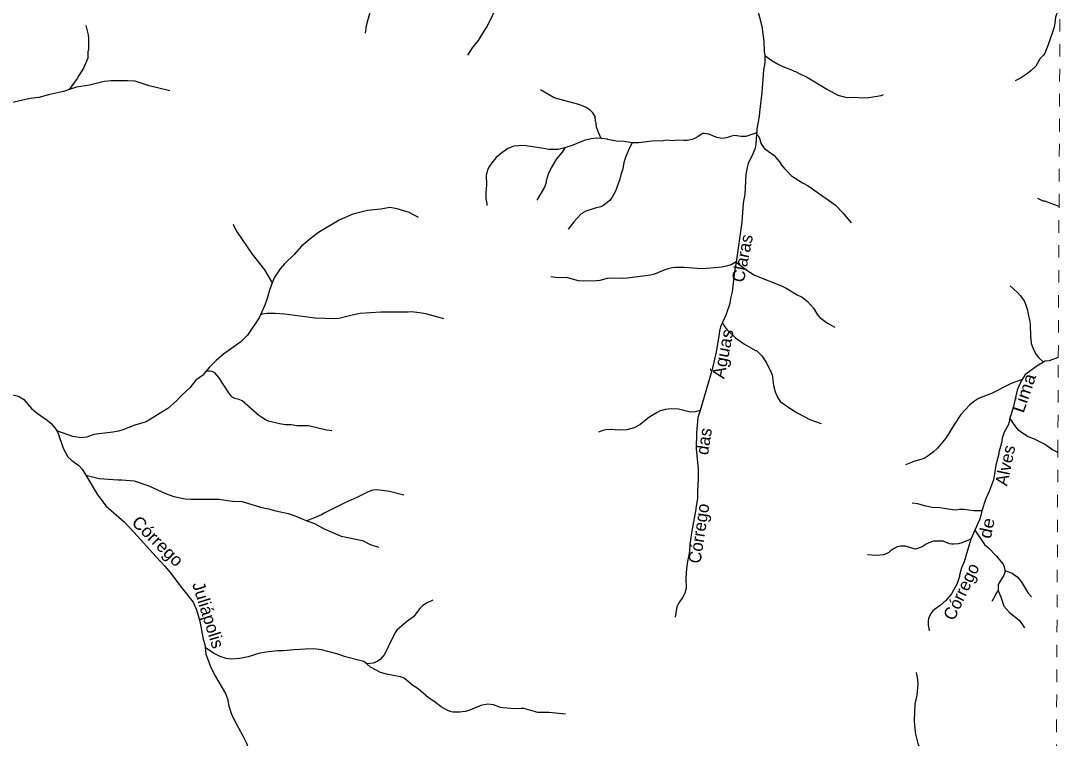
# Model space of a CAD drawing. Extents: x 551.6 to 577.6, y 7567 to 7594.7.
# Drawn here: x 569.17 to 577.56, y 7573.99 to 7579.74 of the extents above; entities that cross this region are included whole.
import ezdxf
from ezdxf.enums import TextEntityAlignment as Align

# ---------------------------------------------------------------- set-up
doc = ezdxf.new("R2010")
doc.units = 0
doc.header["$LTSCALE"] = 0.04
doc.linetypes.add('SHORT_DASHED', pattern=[2.7, 1.5, -1.2])
doc.layers.add('53', color=7, linetype='SHORT_DASHED', lineweight=13)
doc.layers.add('7', color=7, linetype='Continuous', lineweight=25)
doc.layers.add('61', color=7, linetype='Continuous')

msp = doc.modelspace()

# ---------------------------------------------------------------- linework, layer by layer
at = {"layer": '53'}
msp.add_lwpolyline([(577.4204, 7566.9518), (577.4226, 7567.3928), (577.4384, 7570.6314), (577.4446, 7571.9213), (577.4462, 7572.242), (577.4659, 7576.2813), (577.4696, 7577.0412), (577.4755, 7578.252), (577.4832, 7579.8317), (577.4989, 7583.0336), (577.5065, 7584.6034), (577.518, 7586.9644), (577.5184, 7587.0352), (577.519, 7587.1599), (577.5202, 7587.417), (577.5286, 7589.1281), (577.5292, 7589.2596), (577.5446, 7592.4063), (577.549, 7593.3187), (577.5554, 7594.6251)], dxfattribs=at)
at = {"layer": '7'}
msp.add_line((574.8908, 7577.8065), (574.8913, 7577.8061), dxfattribs=at)
for points in [[(574.8818, 7580.4167), (574.9687, 7580.1784), (575.0234, 7579.9611), (575.0572, 7579.8501), (575.0967, 7579.6939), (575.1136, 7579.5732), (575.1152, 7579.4944), (575.1196, 7579.461)], [(572.1544, 7580.2464), (572.1221, 7580.1929), (572.1109, 7580.1663), (572.1101, 7580.1462), (572.1004, 7580.1124), (572.0859, 7580.0336), (572.0014, 7579.9128), (571.9676, 7579.834), (571.9298, 7579.6972), (571.9201, 7579.64)], [(573.1451, 7580.075), (573.0573, 7580.0054), (573.0251, 7579.9611), (572.8972, 7579.6955), (572.8778, 7579.6682), (572.8263, 7579.5813), (572.7764, 7579.5201), (572.7394, 7579.463)], [(577.4832, 7579.8317), (577.4757, 7579.8275), (577.4604, 7579.805), (577.4475, 7579.7664), (577.4427, 7579.7181), (577.4354, 7579.6859), (577.3895, 7579.5443), (577.3614, 7579.4774), (577.3517, 7579.4622), (577.3236, 7579.4348), (577.289, 7579.3744), (577.2535, 7579.339), (577.2238, 7579.3157), (577.1666, 7579.2786), (577.1232, 7579.2577)], [(569.6844, 7579.6996), (569.7029, 7579.6263), (569.7069, 7579.5974), (569.7069, 7579.533), (569.7053, 7579.4992), (569.7021, 7579.4943), (569.7005, 7579.4388), (569.6675, 7579.3575), (569.6281, 7579.2996), (569.616, 7579.2754), (569.5521, 7579.1871)], [(575.1196, 7579.461), (575.12, 7579.401), (575.1104, 7579.3414)], [(575.1196, 7579.461), (575.1756, 7579.4203), (575.2158, 7579.3961), (575.2633, 7579.372), (575.347, 7579.3398), (575.3526, 7579.335), (575.3655, 7579.3326), (575.4049, 7579.3092), (575.4532, 7579.2883), (575.6206, 7579.1869), (575.7059, 7579.1418), (575.7542, 7579.129), (575.7832, 7579.1249), (575.846, 7579.1257), (575.891, 7579.1217), (575.9538, 7579.1249)], [(575.1104, 7579.3414), (575.0975, 7579.1636), (575.0766, 7579.0066), (575.0749, 7578.9728), (575.0572, 7578.8714), (575.0554, 7578.8444), (575.0545, 7578.8313)], [(570.3564, 7579.1773), (570.1914, 7579.2159), (570.0804, 7579.2545), (570.0176, 7579.2577), (569.8872, 7579.2577), (569.8309, 7579.2505), (569.7134, 7579.2223), (569.6104, 7579.2054), (569.5521, 7579.1871)], [(569.5521, 7579.1871), (569.5057, 7579.1724), (569.3866, 7579.1459)], [(573.8107, 7578.7942), (573.7889, 7578.8425), (573.7736, 7578.8859), (573.7688, 7578.9221), (573.7647, 7578.931), (573.7615, 7578.972), (573.743, 7579.0002), (573.7237, 7579.0187), (573.6907, 7579.0428), (573.6617, 7579.0581), (573.6118, 7579.0742), (573.541, 7579.0903), (573.4331, 7579.1217), (573.3245, 7579.1853)], [(569.3866, 7579.1459), (569.3078, 7579.1241), (569.2402, 7579.1145), (569.0776, 7579.0774), (568.9247, 7579.0171), (568.8571, 7578.9817), (568.7943, 7578.943), (568.651, 7578.832), (568.6289, 7578.8084)], [(575.9538, 7579.1249), (576.0504, 7579.1394), (576.0705, 7579.1467)], [(575.0554, 7578.8444), (575.0403, 7578.8344), (574.9687, 7578.8119), (574.9301, 7578.8111), (574.8786, 7578.8183), (574.8528, 7578.8135), (574.8142, 7578.8006), (574.7756, 7578.7942), (574.7369, 7578.8022), (574.6726, 7578.8288), (574.6339, 7578.836), (574.6219, 7578.8344), (574.5873, 7578.8102), (574.5631, 7578.7974), (574.5374, 7578.7877), (574.4987, 7578.7789), (574.473, 7578.7781), (574.4215, 7578.7829), (574.3828, 7578.7773), (574.3313, 7578.7813), (574.3056, 7578.7773), (574.2154, 7578.7732), (574.1112, 7578.7617), (574.0581, 7578.7602)], [(573.776, 7578.7974), (573.7309, 7578.7925), (573.6746, 7578.7789), (573.5845, 7578.7427), (573.5205, 7578.7215)], [(574.0581, 7578.7602), (574.0359, 7578.7201), (574.0078, 7578.6525), (573.9917, 7578.6042), (573.9836, 7578.5527), (573.9675, 7578.5044), (573.9595, 7578.469), (573.9249, 7578.3725), (573.8991, 7578.3242), (573.8798, 7578.3), (573.8243, 7578.2566), (573.8066, 7578.2477), (573.7615, 7578.2372), (573.6875, 7578.2131), (573.6505, 7578.1914), (573.5901, 7578.127), (573.5458, 7578.069)], [(574.0581, 7578.7602), (573.9949, 7578.77), (573.9305, 7578.7748), (573.8637, 7578.7861), (573.8599, 7578.7896), (573.8107, 7578.7942), (573.776, 7578.7974)], [(575.0545, 7578.8313), (575.0492, 7578.7523), (575.0419, 7578.7185), (575.0242, 7578.6735), (574.9864, 7578.5946), (574.9784, 7578.564), (574.9687, 7578.5061), (574.9591, 7578.3499), (574.9478, 7578.2775)], [(575.0545, 7578.8313), (575.0669, 7578.8167), (575.0766, 7578.7974), (575.0894, 7578.7588), (575.1047, 7578.7314), (575.1176, 7578.7153), (575.194, 7578.6582), (575.2383, 7578.6083), (575.256, 7578.5801), (575.2745, 7578.5584), (575.3341, 7578.4956), (575.421, 7578.4392), (575.4669, 7578.4151), (575.6576, 7578.2839), (575.6858, 7578.2606), (575.7445, 7578.2002), (575.8113, 7578.1206)], [(573.5205, 7578.7215), (573.4654, 7578.7072), (573.3913, 7578.7072), (573.3334, 7578.7185), (573.1901, 7578.7386), (573.1113, 7578.733), (573.0638, 7578.7153), (573.0147, 7578.6807), (572.9704, 7578.6421), (572.9342, 7578.601), (572.9157, 7578.5737), (572.9012, 7578.5447)], [(573.5205, 7578.7215), (573.4975, 7578.6863), (573.4533, 7578.6332), (573.4106, 7578.5608), (573.3849, 7578.5109), (573.3704, 7578.457), (573.3712, 7578.4441), (573.3559, 7578.4047), (573.2964, 7578.3024)], [(572.9012, 7578.5447), (572.8907, 7578.498), (572.8915, 7578.424), (572.8859, 7578.3596), (572.8867, 7578.3145), (572.8939, 7578.2759), (572.894, 7578.259)], [(574.9478, 7578.2775), (574.9365, 7578.1262), (574.8913, 7577.8061)], [(577.4755, 7578.252), (577.3606, 7578.2936), (577.3477, 7578.2944), (577.3045, 7578.3137)], [(572.3491, 7578.1624), (572.2743, 7578.2018), (572.1761, 7578.2332), (572.1181, 7578.2437), (572.0473, 7578.2292), (571.9395, 7578.2195), (571.8236, 7578.1881), (571.7117, 7578.1415), (571.5467, 7578.0433), (571.4775, 7577.9902), (571.4115, 7577.9338), (571.3519, 7577.867), (571.2763, 7577.7922)], [(570.8643, 7578.1093), (570.8739, 7578.0827), (570.8956, 7578.0441), (571.0163, 7577.8678), (571.1153, 7577.7447), (571.1756, 7577.6395)], [(571.2763, 7577.7922), (571.2417, 7577.752), (571.1934, 7577.6787), (571.1756, 7577.6395)], [(574.8908, 7577.8065), (574.8496, 7577.7849), (574.811, 7577.7721), (574.7756, 7577.7656), (574.6532, 7577.7535), (574.6162, 7577.7519), (574.4714, 7577.7624), (574.4054, 7577.7624), (574.3764, 7577.7592), (574.3185, 7577.7431), (574.238, 7577.7093), (574.2042, 7577.7004), (574.0175, 7577.6771)], [(574.8913, 7577.8061), (574.877, 7577.7302), (574.8576, 7577.5677), (574.8448, 7577.5129), (574.8399, 7577.4727), (574.8094, 7577.3809), (574.7822, 7577.3226)], [(574.8913, 7577.8061), (574.9768, 7577.7407), (575.0379, 7577.702), (575.2528, 7577.6143), (575.2906, 7577.5966), (575.3792, 7577.5443), (575.4194, 7577.5242), (575.4612, 7577.4888), (575.5087, 7577.4365), (575.5409, 7577.3842), (575.5594, 7577.3624), (575.6206, 7577.3165), (575.6794, 7577.2836)], [(574.0175, 7577.6771), (573.9772, 7577.6731), (573.8774, 7577.6771), (573.8581, 7577.6755), (573.8002, 7577.6578), (573.7728, 7577.6546), (573.6666, 7577.653), (573.6279, 7577.6562), (573.5314, 7577.6827), (573.4638, 7577.6803), (573.4066, 7577.6868)], [(571.1756, 7577.6395), (571.154, 7577.5805), (571.1363, 7577.5129), (571.1185, 7577.4614), (571.0842, 7577.3843)], [(577.0845, 7577.6143), (577.1441, 7577.5612), (577.165, 7577.5379), (577.1908, 7577.5033), (577.2012, 7577.484), (577.2238, 7577.4212), (577.2278, 7577.3874), (577.2415, 7577.3311), (577.2447, 7577.3085), (577.2463, 7577.2039), (577.2495, 7577.1975), (577.2527, 7577.1508), (577.256, 7577.1492), (577.2592, 7577.1331), (577.2729, 7577.0993), (577.293, 7577.0655), (577.3115, 7577.0413), (577.3512, 7577.0045)], [(571.0842, 7577.3843), (571.0727, 7577.3584), (570.9801, 7577.22), (570.9246, 7577.1668), (570.787, 7577.0687), (570.7274, 7577.018), (570.6711, 7576.9608), (570.6484, 7576.9313)], [(571.2779, 7577.3874), (571.2007, 7577.3946), (571.1363, 7577.3938), (571.0952, 7577.389), (571.0842, 7577.3843)], [(572.5519, 7577.3504), (572.4079, 7577.3906), (572.3563, 7577.4002), (572.292, 7577.4075), (572.2662, 7577.4043), (572.0473, 7577.4043), (571.8799, 7577.393), (571.8284, 7577.3833), (571.7093, 7577.3536), (571.6835, 7577.3503), (571.5194, 7577.356), (571.2779, 7577.3874)], [(574.7822, 7577.3226), (574.7659, 7577.2876), (574.7562, 7577.2538), (574.7514, 7577.2136)], [(574.7822, 7577.3226), (574.7957, 7577.2948), (574.815, 7577.2658), (574.8858, 7577.1999), (574.9575, 7577.1475), (575.0444, 7577.0984), (575.0524, 7577.0968), (575.0951, 7577.055), (575.1345, 7576.9995), (575.1715, 7576.9222), (575.178, 7576.9029), (575.1908, 7576.8176), (575.2021, 7576.7661), (575.2214, 7576.725), (575.244, 7576.6888), (575.3357, 7576.6244), (575.3856, 7576.5971)], [(574.7514, 7577.2136), (574.7305, 7577.088), (574.6999, 7576.9464), (574.6035, 7576.6173)], [(577.3512, 7577.0045), (577.297, 7576.9721), (577.2197, 7576.9158), (577.2028, 7576.8996), (577.1808, 7576.8652)], [(577.4696, 7577.0412), (577.3958, 7577.016), (577.3654, 7577.0129), (577.3512, 7577.0045)], [(570.6484, 7576.9313), (570.618, 7576.8964), (570.5657, 7576.8594), (570.5166, 7576.7999), (570.4522, 7576.7387), (570.4103, 7576.6936)], [(570.6952, 7576.9294), (570.6727, 7576.9327), (570.6484, 7576.9313)], [(571.6538, 7576.4538), (571.6111, 7576.4594), (571.4662, 7576.4932), (571.3745, 7576.494), (571.3294, 7576.5013), (571.2844, 7576.5029), (571.2361, 7576.5101), (571.1459, 7576.5319), (571.1234, 7576.5415), (571.0928, 7576.56), (571.0711, 7576.5777), (570.9375, 7576.6944), (570.9125, 7576.7065), (570.8787, 7576.7146), (570.8546, 7576.7258), (570.8296, 7576.758), (570.7507, 7576.8812), (570.7169, 7576.9182), (570.6952, 7576.9294)], [(568.6786, 7576.8276), (568.7187, 7576.8047), (568.7669, 7576.7822), (568.8458, 7576.7612), (568.8683, 7576.758), (569.0341, 7576.7548), (569.1355, 7576.7339), (569.1549, 7576.7274), (569.1886, 7576.7049), (569.2506, 7576.6341)], [(577.1808, 7576.8652), (577.087, 7576.8296), (576.9341, 7576.7532), (576.831, 7576.7121), (576.79, 7576.6864), (576.7586, 7576.6598), (576.6902, 7576.5842), (576.6395, 7576.5085), (576.5703, 7576.3959), (576.5018, 7576.3146), (576.4705, 7576.2856), (576.4286, 7576.2534), (576.3948, 7576.2333), (576.3127, 7576.21), (576.2476, 7576.1834)], [(577.1808, 7576.8652), (577.1642, 7576.8353), (577.1401, 7576.779), (577.1079, 7576.6373), (577.0826, 7576.5556)], [(570.4103, 7576.6936), (570.3403, 7576.6341), (570.1673, 7576.5254), (570.0772, 7576.4989), (569.9806, 7576.4618), (569.9468, 7576.4522), (569.9017, 7576.4425), (569.7488, 7576.4248), (569.6925, 7576.4039), (569.6474, 7576.3991), (569.5798, 7576.4079), (569.4526, 7576.4534)], [(569.2506, 7576.6341), (569.2941, 7576.5946), (569.3754, 7576.5407), (569.4075, 7576.5118), (569.4357, 7576.4796), (569.4526, 7576.4534)], [(574.6035, 7576.6173), (574.5631, 7576.6075), (574.5261, 7576.6043), (574.4295, 7576.6284), (574.3716, 7576.6292), (574.3233, 7576.6252), (574.2758, 7576.6115), (574.2581, 7576.6019), (574.1913, 7576.5617), (574.1189, 7576.5013), (574.0738, 7576.4771), (574.0158, 7576.4635), (573.9597, 7576.4586), (573.8806, 7576.4643), (573.8468, 7576.4618), (573.8243, 7576.4578), (573.7897, 7576.445)], [(574.6035, 7576.6173), (574.584, 7576.5601), (574.5727, 7576.4377), (574.5719, 7576.3122), (574.58, 7576.1995), (574.5872, 7576.1512)], [(575.3856, 7576.5971), (575.4806, 7576.5455), (575.5699, 7576.5134)], [(577.0826, 7576.5556), (577.0708, 7576.5053), (577.037, 7576.4442), (577.0209, 7576.3959), (577.0145, 7576.3572), (576.9944, 7576.28), (576.9944, 7576.2703), (576.9694, 7576.1786), (576.9582, 7576.111)], [(577.4659, 7576.2813), (577.4218, 7576.3025), (577.359, 7576.3484), (577.2729, 7576.391), (577.2286, 7576.4071), (577.19, 7576.4296), (577.1545, 7576.4578), (577.1288, 7576.4852), (577.0826, 7576.5556)], [(569.4526, 7576.4534), (569.4607, 7576.4409), (569.5033, 7576.3154), (569.5419, 7576.2462), (569.5725, 7576.2164), (569.6281, 7576.177), (569.6554, 7576.1464), (569.684, 7576.0985)], [(574.5872, 7576.1512), (574.5872, 7576.0691), (574.58, 7575.9677), (574.58, 7575.913), (574.5679, 7575.8341), (574.5687, 7575.8245), (574.5389, 7575.6683), (574.5212, 7575.546), (574.5164, 7575.4881), (574.5003, 7575.4092), (574.4923, 7575.3529), (574.4882, 7575.274), (574.4907, 7575.1935), (574.4794, 7575.1533), (574.4633, 7575.1227), (574.4392, 7575.0889)], [(569.684, 7576.0985), (569.7745, 7575.9468), (569.8462, 7575.8534), (569.9926, 7575.7255), (570.0691, 7575.6442)], [(569.684, 7576.0985), (569.7923, 7576.0723), (569.9419, 7576.0619), (569.9741, 7576.0627), (570.0707, 7576.0538), (570.1882, 7576.0144), (570.3218, 7575.9532), (570.3894, 7575.9291), (570.4812, 7575.9098), (570.5295, 7575.9065), (570.5906, 7575.9081)], [(576.9582, 7576.111), (576.9501, 7576.0627), (576.9195, 7575.9758), (576.8874, 7575.9049), (576.857, 7575.8146)], [(570.5906, 7575.9081), (570.75, 7575.9065), (570.8594, 7575.892), (570.9367, 7575.8872), (571.0832, 7575.8422), (571.1475, 7575.8309), (571.2055, 7575.8132), (571.3037, 7575.7915), (571.352, 7575.7762), (571.4553, 7575.7343), (571.4711, 7575.7279)], [(572.2316, 7575.9387), (572.1165, 7575.9693), (572.0167, 7575.9806), (571.9813, 7575.979), (571.9451, 7575.9653), (571.855, 7575.9194), (571.7584, 7575.8768), (571.5934, 7575.7947), (571.5717, 7575.781), (571.5081, 7575.7544), (571.4553, 7575.7343)], [(576.857, 7575.8146), (576.7924, 7575.8132), (576.7135, 7575.8244), (576.6797, 7575.8244), (576.6556, 7575.8196), (576.6234, 7575.8212), (576.522, 7575.8381), (576.456, 7575.8397), (576.3981, 7575.8526), (576.3449, 7575.8711), (576.3007, 7575.876)], [(576.857, 7575.8146), (576.8503, 7575.7762), (576.8383, 7575.7424), (576.8003, 7575.6586), (576.7702, 7575.5859)], [(571.4711, 7575.7279), (571.5145, 7575.711), (571.5886, 7575.6731), (571.7286, 7575.612), (571.9008, 7575.575), (571.9604, 7575.5452), (572.0272, 7575.5219)], [(576.8003, 7575.6586), (576.8777, 7575.5444), (576.9099, 7575.517), (576.971, 7575.4543), (577.0282, 7575.3867), (577.0359, 7575.3662), (577.0414, 7575.3366)], [(570.0691, 7575.6442), (570.247, 7575.4454), (570.3178, 7575.3714), (570.3612, 7575.3191), (570.4498, 7575.1991), (570.5431, 7575.0824), (570.5697, 7575.0213), (570.597, 7574.9311), (570.6252, 7574.7863), (570.6389, 7574.7444), (570.6398, 7574.7202)], [(576.7702, 7575.5859), (576.6974, 7575.5581), (576.6717, 7575.5508), (576.6363, 7575.5468), (576.6177, 7575.546), (576.5993, 7575.5508), (576.5477, 7575.5701), (576.4705, 7575.5701), (576.4319, 7575.5581), (576.4109, 7575.5476), (576.3795, 7575.5251), (576.3353, 7575.509), (576.3224, 7575.5074), (576.2451, 7575.5299), (576.2065, 7575.5299), (576.1808, 7575.5243), (576.1566, 7575.513), (576.1228, 7575.4905), (576.1131, 7575.48), (576.0729, 7575.4623), (576.0085, 7575.4567), (575.9433, 7575.4623)], [(576.7702, 7575.5859), (576.7167, 7575.406), (576.6942, 7575.3561), (576.6797, 7575.2981), (576.6797, 7575.2885), (576.6612, 7575.2321), (576.6145, 7575.1492), (576.5687, 7575.0945), (576.5244, 7575.0551), (576.4785, 7575.0245)], [(577.0414, 7575.3366), (577.0411, 7575.3191), (577.033, 7575.2997), (576.9888, 7575.2233), (576.9893, 7575.1771)], [(577.0414, 7575.3366), (577.1014, 7575.3142), (577.1401, 7575.286), (577.1714, 7575.2482), (577.2286, 7575.1549), (577.2544, 7575.1251)], [(576.9893, 7575.1771), (576.9719, 7575.1533), (576.9622, 7575.1291), (576.9381, 7575.0881)], [(576.9893, 7575.1771), (577.0129, 7575.1179), (577.0338, 7575.0502), (577.0757, 7575.0036), (577.1578, 7574.9368), (577.1996, 7574.8772)], [(572.4618, 7575.0977), (572.4167, 7575.0776), (572.3829, 7575.0551), (572.3587, 7575.0309), (572.3089, 7574.9649), (572.2517, 7574.9239), (572.1752, 7574.8587), (572.1632, 7574.8434), (572.1414, 7574.8032), (572.0746, 7574.6623), (572.0424, 7574.6221), (572.0223, 7574.6092), (571.9861, 7574.5947), (571.9352, 7574.5874)], [(574.4392, 7575.0889), (574.4311, 7575.0776), (574.4166, 7575.0438), (574.4038, 7574.9625)], [(576.4785, 7575.0245), (576.4656, 7575.014), (576.4479, 7574.9923), (576.4302, 7574.9521), (576.4302, 7574.9424), (576.427, 7574.9376), (576.427, 7574.9038), (576.4367, 7574.8531)], [(570.6398, 7574.7202), (570.6453, 7574.6656), (570.6823, 7574.5674)], [(571.4405, 7574.705), (571.352, 7574.7009), (571.2634, 7574.6921), (571.22, 7574.6937), (571.1459, 7574.6857), (571.0767, 7574.6736), (570.985, 7574.6454), (570.9174, 7574.6317), (570.8498, 7574.6269), (570.8079, 7574.6325), (570.7596, 7574.6478), (570.7081, 7574.6752), (570.6398, 7574.7202)], [(571.9352, 7574.5874), (571.9105, 7574.6084), (571.764, 7574.6446), (571.6948, 7574.6688), (571.5709, 7574.7001), (571.5065, 7574.7074), (571.4405, 7574.705)], [(570.6823, 7574.5674), (570.7145, 7574.4998), (570.8031, 7574.3501), (570.8192, 7574.3082), (570.8288, 7574.2503), (570.8505, 7574.1859), (570.8715, 7574.1408), (570.9423, 7574.0121), (570.9713, 7573.9525), (571.0083, 7573.8398), (571.0248, 7573.766)], [(572.473, 7574.2865), (572.4272, 7574.3163), (572.3451, 7574.3887), (572.3024, 7574.4144), (572.2324, 7574.474), (572.205, 7574.4853), (572.0924, 7574.5054), (572.0425, 7574.5183), (571.9644, 7574.5625), (571.9352, 7574.5874)], [(576.3305, 7574.5183), (576.3425, 7574.4627), (576.3441, 7574.4289), (576.3361, 7574.3388), (576.3208, 7574.2648), (576.3159, 7574.1344), (576.3208, 7574.0668), (576.3272, 7574.0265), (576.3489, 7573.9404), (576.353, 7573.9331), (576.3691, 7573.8302), (576.3723, 7573.732), (576.3594, 7573.5598), (576.365, 7573.505)], [(573.5241, 7574.1851), (573.3913, 7574.1996), (573.3044, 7574.1988), (573.1917, 7574.2301), (573.1692, 7574.2317), (573.1161, 7574.2277), (573.0259, 7574.2358), (573.0034, 7574.2398), (572.9471, 7574.2591), (572.902, 7574.2655), (572.8457, 7574.2559), (572.7507, 7574.2148), (572.7217, 7574.206), (572.6799, 7574.2012), (572.6235, 7574.202), (572.6026, 7574.206), (572.572, 7574.2189), (572.5294, 7574.243), (572.473, 7574.2865)]]:
    msp.add_lwpolyline(points, dxfattribs=at)

# ---------------------------------------------------------------- texts
at = {"layer": '61'}
for s, rotation, p in [('Claras', 78.815, (574.9892, 7577.827)), ('das', 81.32, (574.6818, 7576.363)), ('Alves', 78.131, (577.0933, 7576.1679)), ('Córrego', 81.32, (574.6406, 7575.6254)), ('Córrego', 64.571, (576.7378, 7575.1456)), ('Juliápolis', 287.521, (570.6178, 7574.9651))]:
    msp.add_text(s, height=0.1, rotation=rotation, dxfattribs=at).set_placement(p, align=Align.CENTER)
for s, rotation, width, p in [('Águas', 78.815, 1.05, (574.8329, 7577.0621)), ('Lima', 71.083, 1.1, (577.2422, 7576.7414)), ('Córrego', 315.657, 1.05, (570.2255, 7575.5356)), ('de', 78.131, 1.1, (576.9452, 7575.6654))]:
    msp.add_text(s, height=0.1, rotation=rotation, dxfattribs=dict(at, width=width)).set_placement(p, align=Align.CENTER)

doc.saveas('drawing.dxf')
